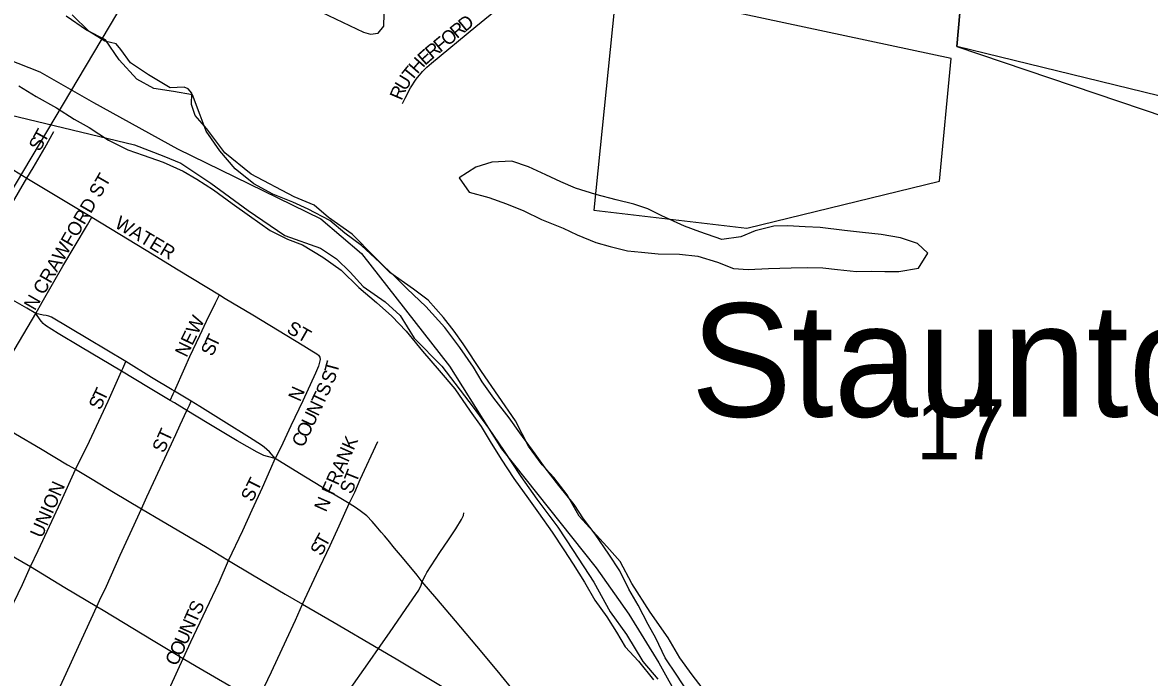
# Model space of a CAD drawing. Extents: x 0 to 680, y 0 to 440.
# Drawn here: x 491.37 to 505.22, y 324.04 to 332.08 of the extents above; entities that cross this region are included whole.
import ezdxf

# ---------------------------------------------------------------- set-up
doc = ezdxf.new("R2010")
doc.units = 0
for name, color, linetype in [('GM_X_City_Street', 7, 'Continuous'), ('GM_X_City_Street_Text', 7, 'Continuous'), ('GM_X_Corporation', 7, 'Continuous'), ('GM_X_Major_River', 7, 'Continuous'), ('GM_X_Minor_Lake', 7, 'Continuous'), ('GM_X_Rail_Line', 7, 'Continuous'), ('GM_X_Section', 7, 'Continuous'), ('GM_X_Section_Text', 7, 'Continuous'), ('GM_X_State_Route', 7, 'Continuous'), ('GM_X_Township', 7, 'Continuous'), ('GM_X_Unincorporated_Text', 7, 'Continuous')]:
    doc.layers.add(name, color=color, linetype=linetype)

msp = doc.modelspace()

# ---------------------------------------------------------------- linework, layer by layer
at = {"layer": 'GM_X_City_Street'}
for points in [[(496.04, 331.09), (496.073, 331.155), (496.137, 331.284), (496.207, 331.389), (496.288, 331.483), (496.338, 331.535), (496.396, 331.586), (496.943, 332.036), (497.47, 332.47), (497.567, 332.56), (497.635, 332.633), (497.695, 332.714), (497.746, 332.8), (497.794, 332.899), (497.839, 333.012), (497.927, 333.282), (497.976, 333.43)], [(490.516, 330.727), (490.942, 330.467), (491.425, 330.173)], [(491.425, 330.173), (491.5, 330.3), (491.645, 330.547), (491.757, 330.744)], [(490.708, 328.995), (490.859, 329.222), (491.218, 329.821), (491.425, 330.173)], [(491.425, 330.173), (492.223, 329.694)], [(491.533, 328.512), (491.614, 328.651), (491.868, 329.092), (492.168, 329.599), (492.223, 329.694)], [(492.223, 329.694), (492.452, 329.556), (492.89, 329.287), (493.284, 329.049), (493.792, 328.74)], [(493.238, 327.556), (493.366, 327.843), (493.427, 327.983), (493.548, 328.24), (493.631, 328.418), (493.743, 328.643), (493.792, 328.74)], [(493.792, 328.74), (493.863, 328.696), (494.201, 328.494), (494.828, 328.113), (494.925, 328.054), (494.986, 328.017), (495.007, 327.999), (495.023, 327.976)], [(490.82, 327.305), (491.176, 327.902), (491.533, 328.512)], [(495.023, 327.976), (495.028, 327.946), (495.022, 327.912), (495.007, 327.866), (494.97, 327.778), (494.815, 327.439), (494.669, 327.132), (494.544, 326.864), (494.475, 326.731)], [(492.022, 326.597), (492.164, 326.883), (492.423, 327.433), (492.588, 327.802)], [(492.588, 327.802), (492.604, 327.837), (492.641, 327.92)], [(493.187, 327.442), (493.223, 327.523), (493.238, 327.556)], [(493.392, 327.32), (493.422, 327.386), (493.443, 327.433)], [(490.82, 327.305), (490.972, 327.213), (491.59, 326.852), (491.925, 326.653), (492.022, 326.597)], [(492.833, 326.112), (492.9, 326.259), (493.256, 327.023), (493.31, 327.143), (493.392, 327.32)], [(495.384, 326.176), (495.454, 326.318), (495.522, 326.474), (495.737, 326.939)], [(493.903, 325.476), (494.079, 325.847), (494.192, 326.1), (494.319, 326.372), (494.421, 326.608), (494.475, 326.731)], [(491.468, 325.402), (491.562, 325.601), (491.842, 326.196), (492.022, 326.595), (492.022, 326.597)], [(492.022, 326.597), (492.228, 326.477), (492.489, 326.317), (492.833, 326.112)], [(490.145, 326.168), (490.642, 325.88), (491.177, 325.573), (491.468, 325.402)], [(494.812, 324.941), (494.985, 325.308), (495.151, 325.663), (495.26, 325.902), (495.384, 326.176)], [(492.283, 324.913), (492.316, 324.987), (492.401, 325.164), (492.572, 325.543), (492.719, 325.861), (492.833, 326.112)], [(492.833, 326.112), (493.081, 325.964), (493.619, 325.649), (493.903, 325.476)], [(496.284, 325.215), (496.306, 325.267), (496.321, 325.298), (496.338, 325.329), (496.5, 325.576), (496.605, 325.731), (496.697, 325.867), (496.765, 325.98), (496.778, 326.005), (496.788, 326.03), (496.796, 326.062)], [(493.347, 324.275), (493.44, 324.479), (493.627, 324.875), (493.786, 325.212), (493.903, 325.476)], [(493.903, 325.476), (494.199, 325.301), (494.599, 325.064), (494.812, 324.941)], [(490.905, 324.183), (491.009, 324.412), (491.159, 324.739), (491.369, 325.184), (491.468, 325.402)], [(491.468, 325.402), (491.892, 325.147), (492.283, 324.913)], [(495.745, 324.395), (495.881, 324.591), (496.086, 324.889), (496.241, 325.114), (496.251, 325.133), (496.266, 325.164), (496.284, 325.215)], [(491.664, 323.557), (491.74, 323.724), (491.907, 324.091), (492.145, 324.608), (492.283, 324.913)], [(492.283, 324.913), (492.361, 324.866), (492.978, 324.495), (493.347, 324.275)], [(494.254, 323.741), (494.431, 324.111), (494.615, 324.507), (494.724, 324.745), (494.781, 324.875), (494.812, 324.941)], [(494.812, 324.941), (494.813, 324.94), (495.201, 324.715), (495.745, 324.395)], [(494.979, 323.302), (495.142, 323.532), (495.359, 323.85), (495.645, 324.25), (495.745, 324.395)], [(495.745, 324.395), (495.961, 324.268), (496.589, 323.892), (496.727, 323.809)], [(492.73, 322.932), (492.809, 323.105), (493.195, 323.943), (493.347, 324.275)], [(493.347, 324.275), (493.505, 324.181), (493.779, 324.022), (494.091, 323.839), (494.254, 323.741)]]:
    msp.add_lwpolyline(points, dxfattribs=at)
at = {"layer": 'GM_X_Corporation'}
msp.add_lwpolyline([(498.391, 329.778), (500.271, 329.558), (502.641, 330.137), (502.781, 331.643), (498.672, 332.523)], close=True, dxfattribs=at)
at = {"layer": 'GM_X_Major_River'}
for points in [[(499.534, 323.88), (499.412, 324.07), (499.27, 324.281), (499.155, 324.524), (499.058, 324.693), (498.937, 324.93), (498.821, 325.127), (498.712, 325.35), (498.577, 325.554), (498.409, 325.799), (498.266, 325.989), (498.15, 326.166), (497.961, 326.398), (497.792, 326.616), (497.669, 326.786), (497.481, 327.044), (497.352, 327.228), (497.163, 327.473), (497.021, 327.67), (496.911, 327.853), (496.743, 328.092), (496.561, 328.337), (496.327, 328.596), (496.098, 328.815), (495.928, 328.98), (495.705, 329.192), (495.535, 329.344), (495.331, 329.496), (495.148, 329.654), (494.883, 329.794), (494.691, 329.878), (494.446, 329.978), (494.215, 330.103), (493.985, 330.289), (493.796, 330.508), (493.628, 330.752), (493.552, 330.948), (493.458, 331.198), (493.225, 331.237), (492.985, 331.276), (492.774, 331.388), (492.558, 331.627), (492.39, 331.871), (492.159, 331.99), (491.909, 332.163)], [(491.327, 331.308), (491.538, 331.176), (491.789, 331.036), (492.007, 330.897), (492.191, 330.793), (492.429, 330.64), (492.667, 330.521), (492.852, 330.456), (493.098, 330.37), (493.343, 330.258), (493.514, 330.16), (493.718, 330.028), (493.949, 329.862), (494.159, 329.71), (494.416, 329.53), (494.627, 329.425), (494.813, 329.354), (495.063, 329.201), (495.287, 329.042), (495.503, 328.829), (495.719, 328.644), (495.909, 328.479), (496.086, 328.294), (496.287, 328.049), (496.489, 327.81), (496.685, 327.585), (496.872, 327.313), (497.008, 327.122), (497.118, 326.939), (497.253, 326.722), (497.408, 326.484), (497.589, 326.233), (497.713, 326.063), (497.881, 325.825), (498.023, 325.607), (498.139, 325.431), (498.275, 325.213), (498.403, 324.99), (498.552, 324.786), (498.668, 324.596), (498.778, 324.419), (498.941, 324.241), (499.123, 324.01)]]:
    msp.add_lwpolyline(points, dxfattribs=at)
at = {"layer": 'GM_X_Minor_Lake'}
for points in [[(495.317, 332.933), (495.172, 332.749), (495.108, 332.57), (495.065, 332.437), (495.021, 332.258), (495.046, 332.21), (495.562, 331.964)], [(495.562, 331.964), (495.649, 331.942), (495.743, 331.953), (495.811, 332.039), (495.818, 332.339), (495.826, 332.674), (495.758, 332.902), (495.56, 333.007), (495.419, 332.984), (495.317, 332.933)], [(502.37, 329.37), (502.158, 329.442), (501.924, 329.481), (501.691, 329.506), (501.471, 329.532), (501.171, 329.565), (500.99, 329.576), (500.77, 329.588), (500.603, 329.585), (500.374, 329.524), (500.199, 329.454), (499.964, 329.42), (499.692, 329.513), (499.506, 329.584), (499.228, 329.711), (499.056, 329.796), (498.884, 329.853), (498.664, 329.905), (498.418, 329.971), (498.166, 330.051), (497.987, 330.128), (497.802, 330.213), (497.59, 330.312), (497.385, 330.383), (497.137, 330.369), (496.942, 330.307), (496.738, 330.178), (496.861, 330.001), (497.1, 329.935), (497.319, 329.857), (497.531, 329.771), (497.749, 329.666), (498.014, 329.559), (498.186, 329.475), (498.418, 329.383), (498.591, 329.332), (498.804, 329.28), (498.977, 329.263), (499.184, 329.244), (499.445, 329.238), (499.671, 329.213), (499.91, 329.14), (500.109, 329.062), (500.289, 329.051), (500.537, 329.065), (500.818, 329.072), (501.012, 329.074), (501.206, 329.07)], [(501.206, 329.07), (501.386, 329.052), (501.62, 329.026), (501.8, 329.029), (501.967, 329.025), (502.141, 329.028), (502.383, 329.069), (502.494, 329.253), (502.37, 329.37)]]:
    msp.add_lwpolyline(points, dxfattribs=at)
at = {"layer": 'GM_X_Rail_Line'}
msp.add_lwpolyline([(494.174, 339.23), (494.368, 338.258), (494.46, 337.706), (494.504, 337.211), (494.495, 336.734), (494.421, 336.034), (494.247, 335.412), (494.07, 334.891), (493.863, 334.451), (493.491, 333.795), (492.717, 332.516), (490.623, 328.994)], dxfattribs=at)
at = {"layer": 'GM_X_Section'}
for points in [[(506.561, 330.885), (502.853, 331.789), (503.581, 339.978)], [(503.581, 339.978), (502.853, 331.789), (506.269, 330.637)], [(499.794, 323.823), (499.598, 324.073), (499.449, 324.283), (499.306, 324.526), (499.085, 324.844), (498.858, 325.195), (498.717, 325.465), (498.553, 325.648), (498.213, 326.022), (498.064, 326.285), (497.901, 326.495), (497.758, 326.651), (497.588, 326.881), (497.427, 327.191), (497.011, 327.799), (496.784, 328.137), (496.674, 328.293), (496.543, 328.462), (496.354, 328.673), (496.176, 328.81), (495.886, 329.015), (495.696, 329.206), (495.421, 329.484), (495.131, 329.69), (494.954, 329.84), (494.709, 329.945), (494.18, 330.222), (493.858, 330.482), (493.636, 330.779), (493.492, 330.942), (493.448, 331.077), (493.451, 331.217), (493.405, 331.271), (493.359, 331.292), (493.185, 331.282), (492.921, 331.44), (492.697, 331.591), (492.58, 331.754), (492.521, 331.822), (492.382, 331.857), (492.19, 331.975), (491.98, 332.179)], [(491.217, 330.951), (492.745, 330.582), (493.109, 330.442), (493.315, 330.358), (493.684, 330.111), (494.145, 329.775), (494.593, 329.467), (495.031, 329.312), (495.228, 329.181), (495.399, 329.018), (495.556, 328.841), (495.826, 328.656), (496.01, 328.486), (496.185, 328.209), (496.525, 327.862), (496.91, 327.361), (497.099, 327.104), (497.28, 326.833), (497.495, 326.509), (497.69, 326.232), (497.95, 325.886), (498.138, 325.602), (498.391, 325.211), (498.592, 324.846), (498.793, 324.569), (498.994, 324.238), (499.177, 324.021)]]:
    msp.add_lwpolyline(points, dxfattribs=at)
at = {"layer": 'GM_X_State_Route'}
for points in [[(491.533, 328.512), (491.423, 328.576), (491.138, 328.74), (490.708, 328.995), (490.678, 329.012)], [(493.443, 327.433), (493.238, 327.556), (493.211, 327.573), (492.957, 327.723), (492.641, 327.92), (492.173, 328.2), (491.728, 328.465), (491.695, 328.477), (491.663, 328.485), (491.626, 328.492), (491.533, 328.512)], [(494.475, 326.731), (494.381, 326.753), (494.336, 326.768), (494.296, 326.787), (494.254, 326.807), (494.007, 326.949), (493.642, 327.17), (493.392, 327.32), (493.238, 327.412), (493.187, 327.442), (492.919, 327.603), (492.588, 327.802), (492.082, 328.103), (491.81, 328.266), (491.653, 328.364), (491.626, 328.386), (491.604, 328.413), (491.589, 328.435), (491.533, 328.512)], [(497.439, 323.841), (497.202, 324.126), (496.953, 324.427), (496.693, 324.736), (496.464, 325.007), (496.284, 325.215), (496.219, 325.298), (496.101, 325.439), (496.015, 325.541), (495.944, 325.628), (495.864, 325.729), (495.82, 325.779), (495.779, 325.827), (495.716, 325.9), (495.669, 325.956), (495.601, 326.026), (495.538, 326.076), (495.476, 326.12), (495.384, 326.176), (495.131, 326.33), (494.774, 326.546), (494.475, 326.731), (494.405, 326.812), (494.373, 326.842), (494.341, 326.87), (494.308, 326.894), (494.161, 326.988), (493.845, 327.184), (493.548, 327.37), (493.443, 327.433)]]:
    msp.add_lwpolyline(points, dxfattribs=at)
at = {"layer": 'GM_X_Township'}
msp.add_lwpolyline([(490.344, 331.964), (491.585, 331.478), (492.243, 331.104), (493.276, 330.535), (495.038, 329.673), (495.535, 329.246), (496.616, 327.862), (497.256, 326.847), (498.421, 325.389), (498.821, 324.819), (499.191, 324.222), (499.694, 323.318)], dxfattribs=at)
msp.add_lwpolyline([(490.344, 331.964), (491.585, 331.478), (492.243, 331.104), (493.276, 330.535), (495.038, 329.673), (495.535, 329.246), (496.616, 327.862), (497.256, 326.847), (498.421, 325.389), (498.821, 324.819), (499.191, 324.222), (499.694, 323.318)], dxfattribs=at)

# ---------------------------------------------------------------- texts
at = {"layer": 'GM_X_City_Street_Text'}
for s, height, rotation, p in [('R', 0.167, 39.5475, (496.709, 331.88)), ('D', 0.167, 39.567, (496.811, 331.964)), ('O', 0.167, 39.567, (496.596, 331.787)), ('R', 0.167, 39.6688, (496.404, 331.628)), ('F', 0.167, 39.5432, (496.506, 331.712)), ('H', 0.167, 48.6804, (496.224, 331.444)), ('E', 0.167, 41.7334, (496.317, 331.55)), ('T', 0.167, 50.8624, (496.151, 331.354)), ('U', 0.167, 58.5228, (496.078, 331.234)), ('R', 0.167, 66.8907, (496.029, 331.118)), ('T', 0.167, 61.1649, (491.642, 330.596)), ('S', 0.167, 59.9264, (491.581, 330.491)), ('N CRAWFORD ST', 0.16689, 60.0015, (491.522, 328.537)), ('WATER', 0.1669, 329.2356, (492.491, 329.576)), ('NEW', 0.1669, 64.2321, (493.387, 327.963)), ('ST', 0.1669, 330.2568, (494.605, 328.284)), ('T', 0.167, 64.5226, (493.754, 328.081)), ('S', 0.167, 65.4882, (493.706, 327.975)), ('T', 0.167, 74.9491, (495.238, 327.766)), ('S', 0.167, 68.1714, (495.188, 327.636)), ('S', 0.167, 65.0464, (495.116, 327.48)), ('T', 0.167, 64.3147, (492.376, 327.421)), ('N', 0.167, 66.0465, (494.781, 327.418)), ('T', 0.167, 64.7328, (495.065, 327.373)), ('S', 0.167, 65.7573, (492.328, 327.315)), ('N', 0.167, 64.7149, (495.003, 327.24)), ('U', 0.167, 64.686, (494.94, 327.107)), ('ST', 0.1669, 64.9823, (493.107, 326.787)), ('O', 0.167, 64.7058, (494.877, 326.975)), ('C', 0.167, 64.7058, (494.821, 326.855)), ('N FRANK', 0.1669, 65.9445, (495.1, 326.063)), ('ST', 0.1669, 68.1961, (495.417, 326.284)), ('UNION', 0.1669, 66.3002, (491.609, 325.743)), ('ST', 0.1669, 63.4349, (494.194, 326.185)), ('S', 0.167, 63.0317, (495.046, 325.524)), ('T', 0.167, 61.0887, (495.098, 325.628)), ('T', 0.167, 65.7934, (493.503, 324.695)), ('S', 0.167, 65.1581, (493.551, 324.801)), ('N', 0.167, 65.8295, (493.443, 324.561)), ('U', 0.167, 65.8087, (493.383, 324.427)), ('O', 0.167, 65.8148, (493.322, 324.293)), ('C', 0.167, 65.8033, (493.268, 324.172))]:
    msp.add_text(s, height=height, rotation=rotation, dxfattribs=at).set_placement(p)
at = {"layer": 'GM_X_Section_Text'}
msp.add_text('17', height=0.7377, rotation=0, dxfattribs=at).set_placement((502.351, 326.718))
at = {"layer": 'GM_X_Unincorporated_Text'}
msp.add_text('Staunton', height=1.3919, rotation=0, dxfattribs=at).set_placement((499.583, 327.243))

doc.saveas('drawing.dxf')
